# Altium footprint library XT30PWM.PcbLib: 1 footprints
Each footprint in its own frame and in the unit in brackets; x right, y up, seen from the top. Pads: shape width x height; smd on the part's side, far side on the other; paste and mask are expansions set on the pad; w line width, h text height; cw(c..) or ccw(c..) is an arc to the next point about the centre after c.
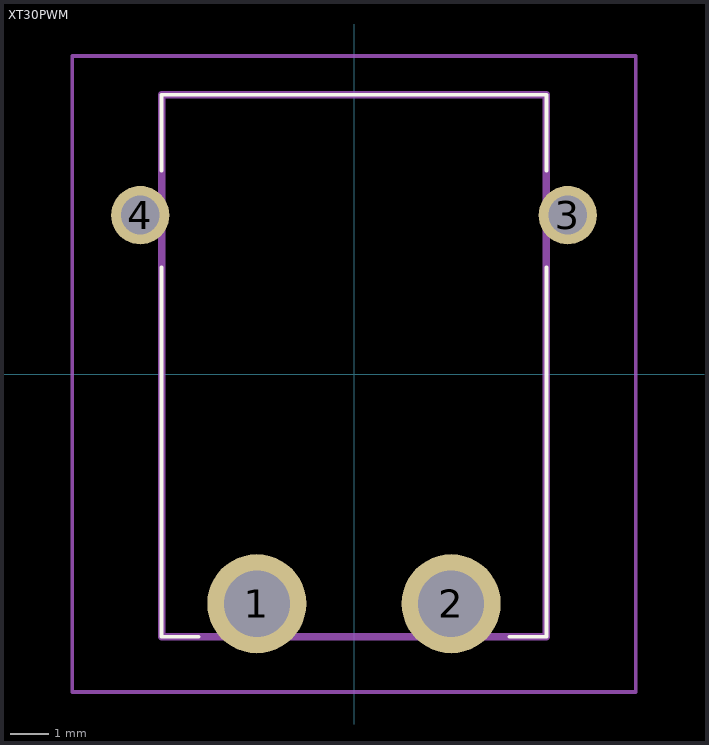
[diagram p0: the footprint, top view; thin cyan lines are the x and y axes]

## XT30PWM [mm]
pads (4):
  round 2.55 hole 1.7: 1(-2.5,-5.912) 2(2.5,-5.912)
  round 1.5 hole 1: 3(5.5,4.088) 4(-5.5,4.088)
Top Overlay:
  lines w0.1: -4.95,2.737 -4.95,-6.762 -4,-6.762 ; -4.95,5.237 -4.95,7.187 4.95,7.187 4.95,5.237 ; 4,-6.762 4.95,-6.762 4.95,2.737
Mechanical 15:
  lines w0.2: -4.95,-6.762 4.95,-6.762 4.95,7.187 -4.95,7.187 -4.95,-6.762
Mechanical 20:
  lines w0.1: -7.25,-8.188 7.25,-8.188 7.25,8.188 -7.25,8.188 -7.25,-8.188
